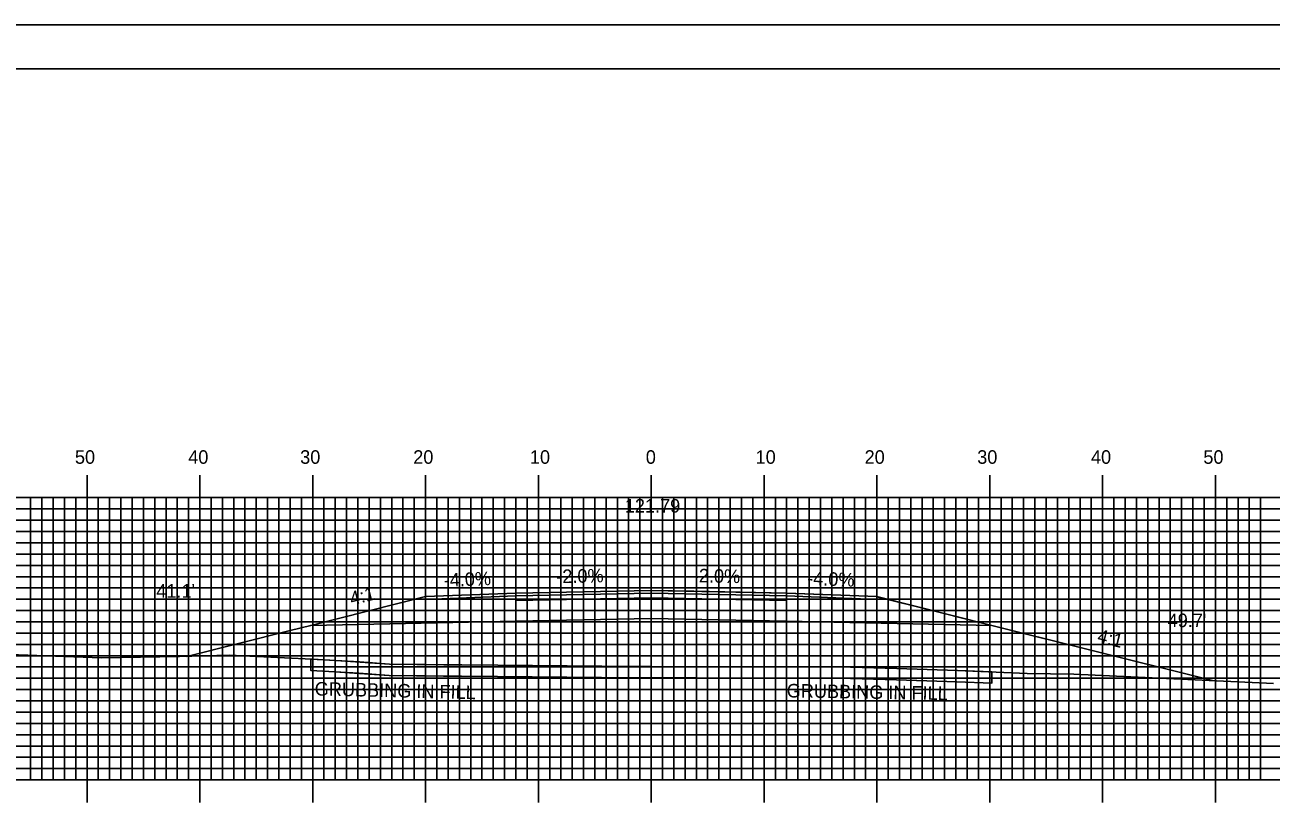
# Model space of a CAD drawing. Extents: x 1771235 to 1771579, y 442591 to 442811.
# Drawn here: x 1771345.6 to 1771456, y 442741.2 to 442810.5 of the extents above; entities that cross this region are included whole.
import ezdxf

# ---------------------------------------------------------------- set-up
doc = ezdxf.new("R2010")
doc.units = 0
for name, color, linetype in [('ANNOTATION', 7, 'Continuous'), ('BORDER', 7, 'Continuous'), ('D_Roadway_Centerline', 7, 'Continuous'), ('D_Roadway_Centerline_Text', 7, 'Continuous'), ('D_Roadway_Edge_Shoulder', 7, 'Continuous'), ('D_Roadway_Edge_TW', 7, 'Continuous'), ('D_Roadway_Pavement', 7, 'Continuous'), ('D_Roadway_SlopeLines', 7, 'Continuous'), ('D_Roadway_SubGrade', 7, 'Continuous'), ('D_Text_Standard', 7, 'Continuous'), ('GRUBBING IN FILL', 7, 'Continuous'), ('H_V ANNOTATION', 7, 'Continuous'), ('MAJOR', 7, 'Continuous'), ('MINOR', 7, 'Continuous'), ('PLOT BOUNDARY', 7, 'Continuous'), ('S_Roadway_Centerline', 7, 'Continuous')]:
    doc.layers.add(name, color=color, linetype=linetype)

msp = doc.modelspace()

# ---------------------------------------------------------------- linework, layer by layer
at = {"layer": 'BORDER'}
msp.add_lwpolyline([(1771251.47, 442596.67), (1771571.47, 442596.67), (1771571.47, 442806.67), (1771251.47, 442806.67)], close=True, dxfattribs=at)
at = {"layer": 'D_Roadway_Centerline'}
msp.add_lwpolyline([(1771359.93, 442754.61), (1771369.07, 442756.9), (1771370.89, 442757.35), (1771381.07, 442759.9), (1771389.07, 442760.22), (1771401.07, 442760.46), (1771404.86, 442760.38), (1771413.07, 442760.22), (1771413.08, 442760.22), (1771421.07, 442759.9), (1771421.07, 442759.89), (1771424.32, 442759.08), (1771431.24, 442757.35), (1771439.44, 442755.3), (1771450.8, 442752.46)], dxfattribs=at)
at = {"layer": 'D_Roadway_Edge_Shoulder'}
for points in [[(1771389.07, 442760.22), (1771381.07, 442759.9), (1771381.07, 442759.65), (1771389.07, 442759.97)], [(1771413.07, 442760.22), (1771421.07, 442759.9), (1771421.07, 442759.65), (1771413.07, 442759.97)]]:
    msp.add_lwpolyline(points, close=True, dxfattribs=at)
at = {"layer": 'D_Roadway_Edge_TW'}
msp.add_lwpolyline([(1771389.07, 442759.97), (1771389.07, 442760.22), (1771401.07, 442760.46), (1771413.07, 442760.22), (1771413.07, 442759.97), (1771401.07, 442760.21)], close=True, dxfattribs=at)
at = {"layer": 'D_Roadway_Pavement'}
msp.add_lwpolyline([(1771389.07, 442759.55), (1771389.07, 442759.97), (1771401.07, 442760.21), (1771413.07, 442759.97), (1771413.07, 442759.55), (1771401.07, 442759.79)], close=True, dxfattribs=at)
at = {"layer": 'D_Roadway_SlopeLines'}
for points in [[(1771381.07, 442759.9), (1771370.89, 442757.35), (1771369.07, 442756.9), (1771359.93, 442754.61)], [(1771421.07, 442759.9), (1771431.24, 442757.35), (1771450.8, 442752.46)]]:
    msp.add_lwpolyline(points, dxfattribs=at)
at = {"layer": 'D_Roadway_SubGrade'}
msp.add_lwpolyline([(1771389.07, 442757.72), (1771370.89, 442757.35), (1771381.07, 442759.9), (1771381.07, 442759.65), (1771389.07, 442759.97), (1771401.07, 442760.21), (1771413.07, 442759.97), (1771421.07, 442759.65), (1771421.07, 442759.9), (1771431.24, 442757.35), (1771413.07, 442757.72), (1771401.07, 442757.96)], close=True, dxfattribs=at)
at = {"layer": 'GRUBBING IN FILL'}
for p, q in [((1771370.89, 442754.36), (1771370.89, 442753.36)), ((1771370.89, 442754.36), (1771370.89, 442753.36)), ((1771431.24, 442753.23), (1771431.24, 442752.23)), ((1771431.24, 442753.23), (1771431.24, 442752.23))]:
    msp.add_line(p, q, dxfattribs=at)
for points in [[(1771370.89, 442754.36), (1771373.11, 442754.24), (1771377.88, 442753.93), (1771382.68, 442753.87), (1771387.47, 442753.82), (1771393.61, 442753.77), (1771399.76, 442753.72), (1771401.07, 442753.72), (1771401.07, 442752.72), (1771399.75, 442752.72), (1771393.6, 442752.77), (1771387.46, 442752.82), (1771382.65, 442752.87), (1771377.84, 442752.93), (1771373.03, 442753.24), (1771370.89, 442753.36)], [(1771370.89, 442754.36), (1771373.11, 442754.24), (1771377.88, 442753.93), (1771382.68, 442753.87), (1771387.47, 442753.82), (1771393.61, 442753.77), (1771399.76, 442753.72), (1771401.07, 442753.72), (1771401.07, 442752.72), (1771399.75, 442752.72), (1771393.6, 442752.77), (1771387.46, 442752.82), (1771382.65, 442752.87), (1771377.84, 442752.93), (1771373.03, 442753.24), (1771370.89, 442753.36)], [(1771401.07, 442753.72), (1771410.44, 442753.69), (1771418.74, 442753.65), (1771422.83, 442753.54), (1771428.2, 442753.36), (1771431.24, 442753.23), (1771431.24, 442752.23), (1771428.16, 442752.36), (1771425.48, 442752.45), (1771422.8, 442752.54), (1771418.72, 442752.65), (1771414.58, 442752.67), (1771410.43, 442752.69), (1771405.09, 442752.71), (1771401.07, 442752.72)], [(1771401.07, 442753.72), (1771410.44, 442753.69), (1771418.74, 442753.65), (1771422.83, 442753.54), (1771428.2, 442753.36), (1771431.24, 442753.23), (1771431.24, 442752.23), (1771428.16, 442752.36), (1771425.48, 442752.45), (1771422.8, 442752.54), (1771418.72, 442752.65), (1771414.58, 442752.67), (1771410.43, 442752.69), (1771405.09, 442752.71), (1771401.07, 442752.72)]]:
    msp.add_lwpolyline(points, close=True, dxfattribs=at)
msp.add_lwpolyline([(1771370.89, 442753.36), (1771375.16, 442753.13), (1771377.84, 442752.93), (1771387.46, 442752.82), (1771399.75, 442752.72), (1771410.43, 442752.69), (1771418.72, 442752.65), (1771422.8, 442752.54), (1771428.16, 442752.36), (1771431.24, 442752.23)], dxfattribs=at)
msp.add_lwpolyline([(1771370.89, 442753.36), (1771375.16, 442753.13), (1771377.84, 442752.93), (1771387.46, 442752.82), (1771399.75, 442752.72), (1771410.43, 442752.69), (1771418.72, 442752.65), (1771422.8, 442752.54), (1771428.16, 442752.36), (1771431.24, 442752.23)], dxfattribs=at)
at = {"layer": 'MAJOR'}
for p, q in [((1771351.07, 442770.67), (1771351.07, 442768.67)), ((1771361.07, 442770.67), (1771361.07, 442768.67)), ((1771371.07, 442770.67), (1771371.07, 442768.67)), ((1771381.07, 442770.67), (1771381.07, 442768.67)), ((1771391.07, 442770.67), (1771391.07, 442768.67)), ((1771401.07, 442770.67), (1771401.07, 442768.67)), ((1771411.07, 442770.67), (1771411.07, 442768.67)), ((1771421.07, 442770.67), (1771421.07, 442768.67)), ((1771431.07, 442770.67), (1771431.07, 442768.67)), ((1771441.07, 442770.67), (1771441.07, 442768.67)), ((1771451.07, 442770.67), (1771451.07, 442768.67)), ((1771261.07, 442768.67), (1771541.07, 442768.67)), ((1771261.07, 442768.67), (1771541.07, 442768.67)), ((1771351.07, 442743.67), (1771351.07, 442768.67)), ((1771361.07, 442743.67), (1771361.07, 442768.67)), ((1771371.07, 442743.67), (1771371.07, 442768.67)), ((1771381.07, 442743.67), (1771381.07, 442768.67)), ((1771391.07, 442743.67), (1771391.07, 442768.67)), ((1771401.07, 442743.67), (1771401.07, 442768.67)), ((1771411.07, 442743.67), (1771411.07, 442768.67)), ((1771421.07, 442743.67), (1771421.07, 442768.67)), ((1771431.07, 442743.67), (1771431.07, 442768.67)), ((1771441.07, 442743.67), (1771441.07, 442768.67)), ((1771451.07, 442743.67), (1771451.07, 442768.67)), ((1771261.07, 442763.67), (1771541.07, 442763.67)), ((1771261.07, 442758.67), (1771541.07, 442758.67)), ((1771261.07, 442753.67), (1771541.07, 442753.67)), ((1771261.07, 442748.67), (1771541.07, 442748.67)), ((1771261.07, 442743.67), (1771541.07, 442743.67)), ((1771261.07, 442743.67), (1771541.07, 442743.67)), ((1771351.07, 442741.66), (1771351.07, 442743.67)), ((1771361.07, 442741.66), (1771361.07, 442743.67)), ((1771371.07, 442741.66), (1771371.07, 442743.67)), ((1771381.07, 442741.66), (1771381.07, 442743.67)), ((1771391.07, 442741.66), (1771391.07, 442743.67)), ((1771401.07, 442741.66), (1771401.07, 442743.67)), ((1771411.07, 442741.66), (1771411.07, 442743.67)), ((1771421.07, 442741.66), (1771421.07, 442743.67)), ((1771431.07, 442741.66), (1771431.07, 442743.67)), ((1771441.07, 442741.66), (1771441.07, 442743.67)), ((1771451.07, 442741.66), (1771451.07, 442743.67))]:
    msp.add_line(p, q, dxfattribs=at)
at = {"layer": 'MINOR'}
for p, q in [((1771346.07, 442743.67), (1771346.07, 442768.67)), ((1771347.07, 442743.67), (1771347.07, 442768.67)), ((1771348.07, 442743.67), (1771348.07, 442768.67)), ((1771349.07, 442743.67), (1771349.07, 442768.67)), ((1771350.07, 442743.67), (1771350.07, 442768.67)), ((1771352.07, 442743.67), (1771352.07, 442768.67)), ((1771353.07, 442743.67), (1771353.07, 442768.67)), ((1771354.07, 442743.67), (1771354.07, 442768.67)), ((1771355.07, 442743.67), (1771355.07, 442768.67)), ((1771356.07, 442743.67), (1771356.07, 442768.67)), ((1771357.07, 442743.67), (1771357.07, 442768.67)), ((1771358.07, 442743.67), (1771358.07, 442768.67)), ((1771359.07, 442743.67), (1771359.07, 442768.67)), ((1771360.07, 442743.67), (1771360.07, 442768.67)), ((1771362.07, 442743.67), (1771362.07, 442768.67)), ((1771363.07, 442743.67), (1771363.07, 442768.67)), ((1771364.07, 442743.67), (1771364.07, 442768.67)), ((1771365.07, 442743.67), (1771365.07, 442768.67)), ((1771366.07, 442743.67), (1771366.07, 442768.67)), ((1771367.07, 442743.67), (1771367.07, 442768.67)), ((1771368.07, 442743.67), (1771368.07, 442768.67)), ((1771369.07, 442743.67), (1771369.07, 442768.67)), ((1771370.07, 442743.67), (1771370.07, 442768.67)), ((1771372.07, 442743.67), (1771372.07, 442768.67)), ((1771373.07, 442743.67), (1771373.07, 442768.67)), ((1771374.07, 442743.67), (1771374.07, 442768.67)), ((1771375.07, 442743.67), (1771375.07, 442768.67)), ((1771376.07, 442743.67), (1771376.07, 442768.67)), ((1771377.07, 442743.67), (1771377.07, 442768.67)), ((1771378.07, 442743.67), (1771378.07, 442768.67)), ((1771379.07, 442743.67), (1771379.07, 442768.67)), ((1771380.07, 442743.67), (1771380.07, 442768.67)), ((1771382.07, 442743.67), (1771382.07, 442768.67)), ((1771383.07, 442743.67), (1771383.07, 442768.67)), ((1771384.07, 442743.67), (1771384.07, 442768.67)), ((1771385.07, 442743.67), (1771385.07, 442768.67)), ((1771386.07, 442743.67), (1771386.07, 442768.67)), ((1771387.07, 442743.67), (1771387.07, 442768.67)), ((1771388.07, 442743.67), (1771388.07, 442768.67)), ((1771389.07, 442743.67), (1771389.07, 442768.67)), ((1771390.07, 442743.67), (1771390.07, 442768.67)), ((1771392.07, 442743.67), (1771392.07, 442768.67)), ((1771393.07, 442743.67), (1771393.07, 442768.67)), ((1771394.07, 442743.67), (1771394.07, 442768.67)), ((1771395.07, 442743.67), (1771395.07, 442768.67)), ((1771396.07, 442743.67), (1771396.07, 442768.67)), ((1771397.07, 442743.67), (1771397.07, 442768.67)), ((1771398.07, 442743.67), (1771398.07, 442768.67)), ((1771399.07, 442743.67), (1771399.07, 442768.67)), ((1771400.07, 442743.67), (1771400.07, 442768.67)), ((1771402.07, 442743.67), (1771402.07, 442768.67)), ((1771403.07, 442743.67), (1771403.07, 442768.67)), ((1771404.07, 442743.67), (1771404.07, 442768.67)), ((1771405.07, 442743.67), (1771405.07, 442768.67)), ((1771406.07, 442743.67), (1771406.07, 442768.67)), ((1771407.07, 442743.67), (1771407.07, 442768.67)), ((1771408.07, 442743.67), (1771408.07, 442768.67)), ((1771409.07, 442743.67), (1771409.07, 442768.67)), ((1771410.07, 442743.67), (1771410.07, 442768.67)), ((1771412.07, 442743.67), (1771412.07, 442768.67)), ((1771413.07, 442743.67), (1771413.07, 442768.67)), ((1771414.07, 442743.67), (1771414.07, 442768.67)), ((1771415.07, 442743.67), (1771415.07, 442768.67)), ((1771416.07, 442743.67), (1771416.07, 442768.67)), ((1771417.07, 442743.67), (1771417.07, 442768.67)), ((1771418.07, 442743.67), (1771418.07, 442768.67)), ((1771419.07, 442743.67), (1771419.07, 442768.67)), ((1771420.07, 442743.67), (1771420.07, 442768.67)), ((1771422.07, 442743.67), (1771422.07, 442768.67)), ((1771423.07, 442743.67), (1771423.07, 442768.67)), ((1771424.07, 442743.67), (1771424.07, 442768.67)), ((1771425.07, 442743.67), (1771425.07, 442768.67)), ((1771426.07, 442743.67), (1771426.07, 442768.67)), ((1771427.07, 442743.67), (1771427.07, 442768.67)), ((1771428.07, 442743.67), (1771428.07, 442768.67)), ((1771429.07, 442743.67), (1771429.07, 442768.67)), ((1771430.07, 442743.67), (1771430.07, 442768.67)), ((1771432.07, 442743.67), (1771432.07, 442768.67)), ((1771433.07, 442743.67), (1771433.07, 442768.67)), ((1771434.07, 442743.67), (1771434.07, 442768.67)), ((1771435.07, 442743.67), (1771435.07, 442768.67)), ((1771436.07, 442743.67), (1771436.07, 442768.67)), ((1771437.07, 442743.67), (1771437.07, 442768.67)), ((1771438.07, 442743.67), (1771438.07, 442768.67)), ((1771439.07, 442743.67), (1771439.07, 442768.67)), ((1771440.07, 442743.67), (1771440.07, 442768.67)), ((1771442.07, 442743.67), (1771442.07, 442768.67)), ((1771443.07, 442743.67), (1771443.07, 442768.67)), ((1771444.07, 442743.67), (1771444.07, 442768.67)), ((1771445.07, 442743.67), (1771445.07, 442768.67)), ((1771446.07, 442743.67), (1771446.07, 442768.67)), ((1771447.07, 442743.67), (1771447.07, 442768.67)), ((1771448.07, 442743.67), (1771448.07, 442768.67)), ((1771449.07, 442743.67), (1771449.07, 442768.67)), ((1771450.07, 442743.67), (1771450.07, 442768.67)), ((1771452.07, 442743.67), (1771452.07, 442768.67)), ((1771453.07, 442743.67), (1771453.07, 442768.67)), ((1771454.07, 442743.67), (1771454.07, 442768.67)), ((1771455.07, 442743.67), (1771455.07, 442768.67)), ((1771261.07, 442767.67), (1771541.07, 442767.67)), ((1771261.07, 442766.67), (1771541.07, 442766.67)), ((1771261.07, 442765.67), (1771541.07, 442765.67)), ((1771261.07, 442764.67), (1771541.07, 442764.67)), ((1771261.07, 442762.67), (1771541.07, 442762.67)), ((1771261.07, 442761.67), (1771541.07, 442761.67)), ((1771261.07, 442760.67), (1771541.07, 442760.67)), ((1771261.07, 442759.67), (1771541.07, 442759.67)), ((1771261.07, 442757.67), (1771541.07, 442757.67)), ((1771261.07, 442756.67), (1771541.07, 442756.67)), ((1771261.07, 442755.67), (1771541.07, 442755.67)), ((1771261.07, 442754.67), (1771541.07, 442754.67)), ((1771261.07, 442752.67), (1771541.07, 442752.67)), ((1771261.07, 442751.67), (1771541.07, 442751.67)), ((1771261.07, 442750.67), (1771541.07, 442750.67)), ((1771261.07, 442749.67), (1771541.07, 442749.67)), ((1771261.07, 442747.67), (1771541.07, 442747.67)), ((1771261.07, 442746.67), (1771541.07, 442746.67)), ((1771261.07, 442745.67), (1771541.07, 442745.67)), ((1771261.07, 442744.67), (1771541.07, 442744.67))]:
    msp.add_line(p, q, dxfattribs=at)
at = {"layer": 'PLOT BOUNDARY'}
msp.add_lwpolyline([(1771235.28, 442590.55), (1771575.28, 442590.55), (1771575.28, 442810.55), (1771235.28, 442810.55)], close=True, dxfattribs=at)
at = {"layer": 'S_Roadway_Centerline'}
msp.add_lwpolyline([(1771342.53, 442754.83), (1771352.36, 442754.47), (1771359.28, 442754.59), (1771363.67, 442754.73), (1771371.01, 442754.35), (1771375.22, 442754.13), (1771377.88, 442753.93), (1771387.47, 442753.82), (1771399.76, 442753.72), (1771410.44, 442753.69), (1771418.74, 442753.65), (1771422.83, 442753.54), (1771428.2, 442753.36), (1771434.39, 442753.1), (1771438.51, 442753.02), (1771456.22, 442752.22)], dxfattribs=at)

# ---------------------------------------------------------------- texts
at = {"layer": 'ANNOTATION'}
for s, rotation, p in [('-4.0%', 2.2907, (1771382.7, 442760.76)), ('-2.0%', 1.1457, (1771392.67, 442761.09)), ('-2.0%', 358.8542, (1771404.75, 442761.18)), ('-4.0%', 357.7095, (1771414.87, 442760.95)), ('4:1', 14.0389, (1771374.52, 442759.12)), ('4:1', 345.9633, (1771440.53, 442755.89))]:
    msp.add_text(s, height=1.2, rotation=rotation, dxfattribs=at).set_placement(p)
at = {"layer": 'D_Roadway_Centerline'}
for s, p in [('C', (1771401.06, 442760.46)), ('L', (1771401.07, 442760.45))]:
    msp.add_text(s, height=0.0146, dxfattribs=at).set_placement(p)
at = {"layer": 'D_Roadway_Centerline_Text'}
msp.add_text('121.79', height=1.2, dxfattribs=at).set_placement((1771398.73, 442767.35))
at = {"layer": 'D_Text_Standard'}
for s, p in [("41.1'", (1771357.21, 442759.81)), ("49.7'", (1771446.84, 442757.2))]:
    msp.add_text(s, height=1.2, dxfattribs=at).set_placement(p)
at = {"layer": 'GRUBBING IN FILL'}
for rotation, p in [(358.649, (1771371.24, 442751.15)), (359.0192, (1771413.07, 442750.98))]:
    msp.add_text('GRUBBING IN FILL', height=1.2, rotation=rotation, dxfattribs=at).set_placement(p)
at = {"layer": 'H_V ANNOTATION'}
for s, p in [('50', (1771350, 442771.67)), ('40', (1771360.04, 442771.67)), ('30', (1771369.96, 442771.67)), ('20', (1771379.98, 442771.67)), ('10', (1771390.32, 442771.67)), ('0', (1771400.59, 442771.67)), ('10', (1771410.32, 442771.67)), ('20', (1771419.98, 442771.67)), ('30', (1771429.96, 442771.67)), ('40', (1771440.04, 442771.67)), ('50', (1771450, 442771.67))]:
    msp.add_text(s, height=1.2, dxfattribs=at).set_placement(p)

doc.saveas('drawing.dxf')
